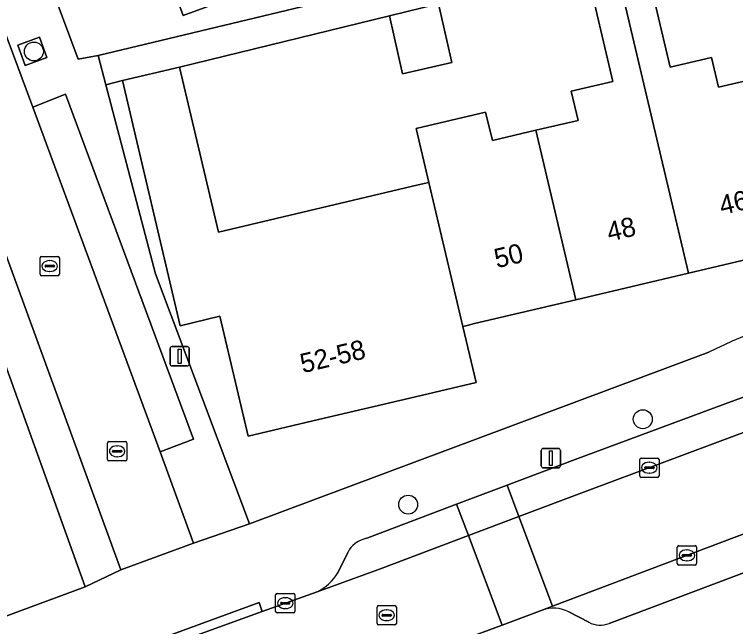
# Model space of a CAD drawing. Extents: x 158472 to 159562, y 388525 to 389606.
# Drawn here: x 159134.37 to 159171.7, y 388714.26 to 388745.92 of the extents above; entities that cross this region are included whole.
import ezdxf

# ---------------------------------------------------------------- set-up
doc = ezdxf.new("R2010")
doc.units = 0
for name, color, linetype in [('IMGEO_Boom', 7, 'Continuous'), ('IMGEO_Erf', 7, 'Continuous'), ('IMGEO_Groenvoorziening', 7, 'Continuous'), ('IMGEO_Kolk', 7, 'Continuous'), ('IMGEO_Lichtmast', 7, 'Continuous'), ('IMGEO_Pand', 7, 'Continuous'), ('IMGEO_Pand_nummerreeks', 7, 'Continuous'), ('IMGEO_Parkeervlak_open', 7, 'Continuous'), ('IMGEO_Rijbaan_lokaal_open', 7, 'Continuous'), ('IMGEO_Rioolput', 7, 'Continuous'), ('IMGEO_Voetpad_open', 7, 'Continuous')]:
    doc.layers.add(name, color=color, linetype=linetype)

msp = doc.modelspace()

# ---------------------------------------------------------------- linework, layer by layer
at = {"layer": 'IMGEO_Boom'}
for centre in [(159135.378, 388744.008), (159166.896, 388724.984), (159154.75, 388720.566)]:
    msp.add_circle(centre, 0.489, dxfattribs=at)
at = {"layer": 'IMGEO_Erf'}
for points in [[(159175.939, 388750), (159175.698, 388751.019), (159166.947, 388748.967), (159168.311, 388743.191), (159170.459, 388743.698), (159170.823, 388742.157), (159173.045, 388742.681), (159175.204, 388743.191), (159174.813, 388744.844), (159177.032, 388745.368)], [(159163.979, 388748.266), (159156.327, 388746.47), (159157.01, 388743.431), (159154.46, 388742.857), (159153.786, 388745.855), (159142.909, 388743.198), (159144.925, 388734.661), (159155.261, 388737.102), (159155.828, 388737.236), (159155.17, 388740.024), (159158.762, 388740.873), (159159.11, 388739.398), (159161.359, 388739.929), (159163.544, 388740.445), (159163.189, 388741.951), (159165.35, 388742.461)]]:
    msp.add_lwpolyline(points, close=True, dxfattribs=at)
for points in [[(159135.295, 388750), (159137.677, 388743.611), (159138.705, 388743.804), (159164.296, 388749.934)], [(159147.79, 388747.598), (159143.098, 388745.87), (159141.577, 388750)], [(159196.529, 388748.231), (159198.597, 388739.472), (159192.637, 388738.064), (159186.796, 388736.685), (159180.954, 388735.305), (159175.112, 388733.925), (159169.27, 388732.546), (159163.428, 388731.166), (159158.186, 388729.928), (159157.805, 388729.838), (159157.587, 388729.786), (159158.27, 388726.892), (159154.834, 388726.08), (159150.112, 388724.965), (159146.469, 388724.104), (159145.004, 388730.308), (159142.954, 388729.823), (159139.96, 388742.501), (159139.106, 388742.277), (159141.671, 388732.512), (159146.544, 388719.568), (159170.31, 388728.457)], [(159090.691, 388698.796), (159138.036, 388716.321), (159133.328, 388729.371), (159130.469, 388728.297), (159129.382, 388731.188)]]:
    msp.add_lwpolyline(points, dxfattribs=at)
msp.add_arc((159185.802, 388696.479), 35.533, 104.3383, 115.8477, dxfattribs=at)
at = {"layer": 'IMGEO_Groenvoorziening'}
msp.add_lwpolyline([(159136.05, 388743.7), (159135.66, 388744.746), (159134.543, 388744.33), (159134.933, 388743.284)], close=True, dxfattribs=at)
at = {"layer": 'IMGEO_Kolk'}
for p, q in [((159135.769, 388733.407), (159136.621, 388733.407)), ((159135.694, 388732.481), (159135.694, 388733.333)), ((159136.182, 388733.187), (159136.207, 388733.187)), ((159136.695, 388733.333), (159136.695, 388732.481)), ((159135.953, 388732.901), (159135.953, 388732.913)), ((159136.391, 388732.864), (159135.993, 388732.864)), ((159135.996, 388732.95), (159136.394, 388732.95)), ((159136.205, 388732.627), (159136.18, 388732.627)), ((159136.437, 388732.913), (159136.437, 388732.901)), ((159136.621, 388732.407), (159135.769, 388732.407)), ((159139.184, 388722.899), (159139.184, 388723.751)), ((159139.259, 388723.825), (159140.111, 388723.825)), ((159140.185, 388723.751), (159140.185, 388722.899)), ((159139.443, 388723.319), (159139.443, 388723.331)), ((159139.486, 388723.368), (159139.884, 388723.368)), ((159139.672, 388723.605), (159139.697, 388723.605)), ((159139.927, 388723.331), (159139.927, 388723.319)), ((159139.881, 388723.282), (159139.483, 388723.282)), ((159139.695, 388723.045), (159139.67, 388723.045)), ((159166.811, 388722.977), (159167.663, 388722.977)), ((159140.111, 388722.825), (159139.259, 388722.825)), ((159166.736, 388722.051), (159166.736, 388722.903)), ((159167.224, 388722.757), (159167.249, 388722.757)), ((159167.737, 388722.903), (159167.737, 388722.051)), ((159166.995, 388722.471), (159166.995, 388722.483)), ((159167.433, 388722.434), (159167.035, 388722.434)), ((159167.038, 388722.52), (159167.436, 388722.52)), ((159167.247, 388722.197), (159167.222, 388722.197)), ((159167.479, 388722.483), (159167.479, 388722.471)), ((159167.663, 388721.977), (159166.811, 388721.977)), ((159168.759, 388718.443), (159169.611, 388718.443)), ((159168.684, 388717.517), (159168.684, 388718.369)), ((159169.172, 388718.223), (159169.197, 388718.223)), ((159169.685, 388718.369), (159169.685, 388717.517)), ((159168.943, 388717.937), (159168.943, 388717.949)), ((159169.381, 388717.9), (159168.983, 388717.9)), ((159168.986, 388717.986), (159169.384, 388717.986)), ((159169.427, 388717.949), (159169.427, 388717.937)), ((159169.611, 388717.443), (159168.759, 388717.443)), ((159169.195, 388717.663), (159169.17, 388717.663)), ((159147.89, 388715.042), (159147.89, 388715.894)), ((159147.965, 388715.968), (159148.817, 388715.968)), ((159148.891, 388715.894), (159148.891, 388715.042)), ((159148.149, 388715.462), (159148.149, 388715.474)), ((159148.192, 388715.511), (159148.59, 388715.511)), ((159148.378, 388715.748), (159148.403, 388715.748)), ((159148.633, 388715.474), (159148.633, 388715.462)), ((159148.587, 388715.425), (159148.189, 388715.425)), ((159148.401, 388715.188), (159148.376, 388715.188)), ((159148.817, 388714.968), (159147.965, 388714.968))]:
    msp.add_line(p, q, dxfattribs=at)
for points in [[(159135.769, 388733.407), (159136.621, 388733.407)], [(159135.694, 388732.481), (159135.694, 388733.333)], [(159136.695, 388733.333), (159136.695, 388732.481)], [(159136.621, 388732.407), (159135.769, 388732.407)], [(159139.184, 388722.899), (159139.184, 388723.751)], [(159139.259, 388723.825), (159140.111, 388723.825)], [(159140.185, 388723.751), (159140.185, 388722.899)], [(159166.811, 388722.977), (159167.663, 388722.977)], [(159140.111, 388722.825), (159139.259, 388722.825)], [(159166.736, 388722.051), (159166.736, 388722.903)], [(159167.737, 388722.903), (159167.737, 388722.051)], [(159167.663, 388721.977), (159166.811, 388721.977)], [(159168.759, 388718.443), (159169.611, 388718.443)], [(159168.684, 388717.517), (159168.684, 388718.369)], [(159169.685, 388718.369), (159169.685, 388717.517)], [(159169.611, 388717.443), (159168.759, 388717.443)], [(159147.89, 388715.042), (159147.89, 388715.894)], [(159147.965, 388715.968), (159148.817, 388715.968)], [(159148.891, 388715.894), (159148.891, 388715.042)], [(159148.817, 388714.968), (159147.965, 388714.968)]]:
    msp.add_lwpolyline(points, dxfattribs=at)
for centre, radius, start, end in [((159135.771, 388733.331), 0.0765, 91.552, 178.448), ((159135.771, 388733.331), 0.0765, 91.552, 178.448), ((159136.619, 388733.331), 0.0765, 1.552, 88.448), ((159136.619, 388733.331), 0.0765, 1.552, 88.448), ((159135.993, 388732.91), 0.0403, 85.8775, 175.7526), ((159135.99, 388732.9), 0.0366, 178.938, 274.7102), ((159136.394, 388732.907), 0.043, 264.8664, 352.4533), ((159136.398, 388732.912), 0.0386, 1.7309, 96.639), ((159135.771, 388732.483), 0.0765, 181.552, 268.448), ((159135.771, 388732.483), 0.0765, 181.552, 268.448), ((159136.619, 388732.483), 0.0765, 271.552, 358.448), ((159136.619, 388732.483), 0.0765, 271.552, 358.448), ((159139.261, 388723.749), 0.0765, 91.552, 178.448), ((159139.261, 388723.749), 0.0765, 91.552, 178.448), ((159140.109, 388723.749), 0.0765, 1.552, 88.448), ((159140.109, 388723.749), 0.0765, 1.552, 88.448), ((159139.483, 388723.328), 0.0403, 85.8775, 175.7526), ((159139.48, 388723.318), 0.0366, 178.938, 274.7102), ((159139.884, 388723.325), 0.043, 264.8664, 352.4533), ((159139.888, 388723.33), 0.0386, 1.7309, 96.639), ((159166.813, 388722.901), 0.0765, 91.552, 178.448), ((159166.813, 388722.901), 0.0765, 91.552, 178.448), ((159167.661, 388722.901), 0.0765, 1.552, 88.448), ((159167.661, 388722.901), 0.0765, 1.552, 88.448), ((159139.261, 388722.901), 0.0765, 181.552, 268.448), ((159139.261, 388722.901), 0.0765, 181.552, 268.448), ((159140.109, 388722.901), 0.0765, 271.552, 358.448), ((159140.109, 388722.901), 0.0765, 271.552, 358.448), ((159167.035, 388722.48), 0.0403, 85.8775, 175.7526), ((159167.032, 388722.47), 0.0366, 178.938, 274.7102), ((159167.436, 388722.477), 0.043, 264.8664, 352.4533), ((159167.44, 388722.482), 0.0386, 1.7309, 96.639), ((159166.813, 388722.053), 0.0765, 181.552, 268.448), ((159166.813, 388722.053), 0.0765, 181.552, 268.448), ((159167.661, 388722.053), 0.0765, 271.552, 358.448), ((159167.661, 388722.053), 0.0765, 271.552, 358.448), ((159168.761, 388718.367), 0.0765, 91.552, 178.448), ((159168.761, 388718.367), 0.0765, 91.552, 178.448), ((159169.609, 388718.367), 0.0765, 1.552, 88.448), ((159169.609, 388718.367), 0.0765, 1.552, 88.448), ((159168.983, 388717.946), 0.0403, 85.8775, 175.7526), ((159168.98, 388717.936), 0.0366, 178.938, 274.7102), ((159169.384, 388717.943), 0.043, 264.8664, 352.4533), ((159169.388, 388717.948), 0.0386, 1.7309, 96.639), ((159168.761, 388717.519), 0.0765, 181.552, 268.448), ((159168.761, 388717.519), 0.0765, 181.552, 268.448), ((159169.609, 388717.519), 0.0765, 271.552, 358.448), ((159169.609, 388717.519), 0.0765, 271.552, 358.448), ((159147.967, 388715.892), 0.0765, 91.552, 178.448), ((159147.967, 388715.892), 0.0765, 91.552, 178.448), ((159148.815, 388715.892), 0.0765, 1.552, 88.448), ((159148.815, 388715.892), 0.0765, 1.552, 88.448), ((159148.189, 388715.471), 0.0403, 85.8775, 175.7526), ((159148.186, 388715.461), 0.0366, 178.938, 274.7102), ((159148.59, 388715.468), 0.043, 264.8664, 352.4533), ((159148.594, 388715.473), 0.0386, 1.7309, 96.639), ((159147.967, 388715.044), 0.0765, 181.552, 268.448), ((159147.967, 388715.044), 0.0765, 181.552, 268.448), ((159148.815, 388715.044), 0.0765, 271.552, 358.448), ((159148.815, 388715.044), 0.0765, 271.552, 358.448)]:
    msp.add_arc(centre, radius, start, end, dxfattribs=at)
for centre, major_axis, ratio, start_param, end_param in [((159136.181, 388732.907), (-0.387, 0.002), 0.722429, 4.712389, 7.853982), ((159136.206, 388732.907), (-0.39, 0.002), 0.717154, 1.570796, 4.712389), ((159139.671, 388723.325), (-0.387, 0.002), 0.722429, 4.712389, 7.853982), ((159139.696, 388723.325), (-0.39, 0.002), 0.717154, 1.570796, 4.712389), ((159167.223, 388722.477), (-0.387, 0.002), 0.722429, 4.712389, 7.853982), ((159167.248, 388722.477), (-0.39, 0.002), 0.717154, 1.570796, 4.712389), ((159169.171, 388717.943), (-0.387, 0.002), 0.722429, 4.712389, 7.853982), ((159169.196, 388717.943), (-0.39, 0.002), 0.717154, 1.570796, 4.712389), ((159148.377, 388715.468), (-0.387, 0.002), 0.722429, 4.712389, 7.853982), ((159148.402, 388715.468), (-0.39, 0.002), 0.717154, 1.570796, 4.712389)]:
    msp.add_ellipse(centre, major_axis=major_axis, ratio=ratio, start_param=start_param, end_param=end_param, dxfattribs=at)
at = {"layer": 'IMGEO_Lichtmast'}
for p, q in [((159142.425, 388727.84), (159142.425, 388728.64)), ((159142.425, 388728.64), (159142.425, 388727.84)), ((159142.525, 388728.74), (159143.315, 388728.74)), ((159143.315, 388728.74), (159142.525, 388728.74)), ((159143.415, 388728.64), (159143.415, 388727.84)), ((159143.415, 388727.84), (159143.415, 388728.64)), ((159143.315, 388727.74), (159142.525, 388727.74)), ((159142.525, 388727.74), (159143.315, 388727.74)), ((159161.642, 388722.57), (159161.642, 388723.37)), ((159161.642, 388723.37), (159161.642, 388722.57)), ((159161.742, 388723.47), (159162.532, 388723.47)), ((159162.532, 388723.47), (159161.742, 388723.47)), ((159162.632, 388723.37), (159162.632, 388722.57)), ((159162.632, 388722.57), (159162.632, 388723.37)), ((159162.532, 388722.47), (159161.742, 388722.47)), ((159161.742, 388722.47), (159162.532, 388722.47))]:
    msp.add_line(p, q, dxfattribs=at)
for points in [[(159142.845, 388728.615), (159142.995, 388728.615), (159142.995, 388727.865), (159142.845, 388727.865), (159142.845, 388728.615)], [(159162.062, 388723.345), (159162.212, 388723.345), (159162.212, 388722.595), (159162.062, 388722.595), (159162.062, 388723.345)]]:
    msp.add_lwpolyline(points, dxfattribs=at)
for centre, start, end in [((159142.525, 388728.64), 90, 180), ((159142.525, 388728.64), 90, 180), ((159143.315, 388728.64), 0, 90), ((159143.315, 388728.64), 360, 90), ((159142.525, 388727.84), 180, 270), ((159142.525, 388727.84), 180, 270), ((159143.315, 388727.84), 270, 0), ((159143.315, 388727.84), 270, 0), ((159161.742, 388723.37), 90, 180), ((159161.742, 388723.37), 90, 180), ((159162.532, 388723.37), 0, 90), ((159162.532, 388723.37), 360, 90), ((159161.742, 388722.57), 180, 270), ((159161.742, 388722.57), 180, 270), ((159162.532, 388722.57), 270, 0), ((159162.532, 388722.57), 270, 0)]:
    msp.add_arc(centre, 0.1, start, end, dxfattribs=at)
at = {"layer": 'IMGEO_Pand'}
for points in [[(159150.965, 388750), (159149.453, 388754.103), (159149.236, 388754.023), (159141.187, 388751.058), (159141.577, 388750), (159143.098, 388745.87), (159147.79, 388747.598), (159151.364, 388748.915)], [(159175.112, 388733.925), (159173.045, 388742.681), (159170.823, 388742.157), (159170.459, 388743.698), (159168.311, 388743.191), (159166.947, 388748.967), (159165.475, 388748.619), (159169.27, 388732.546)], [(159161.359, 388739.929), (159163.428, 388731.166), (159169.27, 388732.546), (159165.475, 388748.619), (159163.979, 388748.266), (159165.35, 388742.461), (159163.189, 388741.951), (159163.544, 388740.445)], [(159154.46, 388742.857), (159157.01, 388743.431), (159156.327, 388746.47), (159153.786, 388745.855)], [(159155.828, 388737.236), (159155.261, 388737.102), (159144.925, 388734.661), (159142.909, 388743.198), (159139.96, 388742.501), (159142.954, 388729.823), (159145.004, 388730.308), (159146.469, 388724.104), (159150.112, 388724.965), (159154.834, 388726.08), (159158.27, 388726.892), (159157.587, 388729.786)], [(159161.359, 388739.929), (159159.11, 388739.398), (159158.762, 388740.873), (159155.17, 388740.024), (159155.828, 388737.236), (159157.587, 388729.786), (159157.805, 388729.838), (159158.186, 388729.928), (159163.428, 388731.166)]]:
    msp.add_lwpolyline(points, close=True, dxfattribs=at)
at = {"layer": 'IMGEO_Parkeervlak_open'}
for points in [[(159137.016, 388741.799), (159135.321, 388741.121), (159141.907, 388723.296), (159143.633, 388723.953)], [(159159.88, 388721.567), (159157.262, 388720.582), (159157.871, 388718.963), (159160.489, 388719.947)]]:
    msp.add_lwpolyline(points, close=True, dxfattribs=at)
for points in [[(159178.125, 388728.335), (159171.168, 388725.789), (159163.405, 388722.893), (159159.88, 388721.567), (159160.489, 388719.947), (159164.012, 388721.272), (159171.791, 388724.175), (159178.672, 388726.694)], [(159157.871, 388718.963), (159157.262, 388720.582), (159152.661, 388718.852), (159152.546, 388718.81)], [(159173.174, 388719.453), (159162.231, 388715.317), (159161.695, 388715.114)], [(159150.038, 388716.062), (159153.26, 388717.228), (159157.871, 388718.963)], [(159151.625, 388718.089), (159151.108, 388717.042)], [(159165.157, 388714.414), (159173.849, 388717.701)], [(159163.061, 388715.018), (159164.101, 388714.479)]]:
    msp.add_lwpolyline(points, dxfattribs=at)
for centre, radius, start, end in [((159152.873, 388717.444), 1.405, 103.4532, 152.6577), ((159148.968, 388718.304), 2.484, 295.5053, 329.4671), ((159162.268, 388713.494), 1.718, 62.4901, 109.4699), ((159164.704, 388715.665), 1.33, 243.0418, 289.9136)]:
    msp.add_arc(centre, radius, start, end, dxfattribs=at)
at = {"layer": 'IMGEO_Rijbaan_lokaal_open'}
for points in [[(159135.321, 388741.121), (159134, 388744.695), (159130.295, 388743.326), (159131.692, 388739.556), (159139.87, 388717.199), (159143.641, 388718.565), (159141.907, 388723.296)], [(159160.489, 388719.947), (159157.871, 388718.963), (159159.611, 388714.339), (159161.695, 388715.114), (159162.231, 388715.317)], [(159150.006, 388710.766), (159150.389, 388710.909), (159157.459, 388713.538), (159159.611, 388714.339), (159157.871, 388718.963), (159153.26, 388717.228), (159150.038, 388716.062), (159147.197, 388715.034), (159144.005, 388713.879), (159139.387, 388712.169), (159134.579, 388710.389), (159133.876, 388710.139), (159126.21, 388707.414), (159121.757, 388705.716), (159123.494, 388701.022), (159138.476, 388706.537), (159145.31, 388709.044)]]:
    msp.add_lwpolyline(points, close=True, dxfattribs=at)
msp.add_lwpolyline([(159178.672, 388726.694), (159171.791, 388724.175), (159164.012, 388721.272), (159160.489, 388719.947), (159162.231, 388715.317), (159173.174, 388719.453)], dxfattribs=at)
at = {"layer": 'IMGEO_Rioolput'}
for p, q in [((159153.139, 388714.418), (159153.139, 388715.27)), ((159153.214, 388715.344), (159154.066, 388715.344)), ((159153.627, 388715.124), (159153.652, 388715.124)), ((159154.14, 388715.27), (159154.14, 388714.418)), ((159153.398, 388714.838), (159153.398, 388714.85)), ((159153.836, 388714.801), (159153.438, 388714.801)), ((159153.441, 388714.887), (159153.839, 388714.887)), ((159153.882, 388714.85), (159153.882, 388714.838)), ((159154.066, 388714.344), (159153.214, 388714.344)), ((159153.65, 388714.564), (159153.625, 388714.564))]:
    msp.add_line(p, q, dxfattribs=at)
for points in [[(159153.139, 388714.418), (159153.139, 388715.27)], [(159153.214, 388715.344), (159154.066, 388715.344)], [(159154.14, 388715.27), (159154.14, 388714.418)], [(159154.066, 388714.344), (159153.214, 388714.344)]]:
    msp.add_lwpolyline(points, dxfattribs=at)
for centre, radius, start, end in [((159153.216, 388715.268), 0.0765, 91.552, 178.448), ((159153.216, 388715.268), 0.0765, 91.552, 178.448), ((159154.064, 388715.268), 0.0765, 1.552, 88.448), ((159154.064, 388715.268), 0.0765, 1.552, 88.448), ((159153.438, 388714.847), 0.0403, 85.8775, 175.7526), ((159153.435, 388714.837), 0.0366, 178.938, 274.7102), ((159153.839, 388714.844), 0.043, 264.8664, 352.4533), ((159153.843, 388714.849), 0.0386, 1.7309, 96.639), ((159153.216, 388714.42), 0.0765, 181.552, 268.448), ((159153.216, 388714.42), 0.0765, 181.552, 268.448), ((159154.064, 388714.42), 0.0765, 271.552, 358.448), ((159154.064, 388714.42), 0.0765, 271.552, 358.448)]:
    msp.add_arc(centre, radius, start, end, dxfattribs=at)
for centre, major_axis, ratio, start_param, end_param in [((159153.626, 388714.844), (-0.387, 0.002), 0.722429, 4.712389, 7.853982), ((159153.651, 388714.844), (-0.39, 0.002), 0.717154, 1.570796, 4.712389)]:
    msp.add_ellipse(centre, major_axis=major_axis, ratio=ratio, start_param=start_param, end_param=end_param, dxfattribs=at)
at = {"layer": 'IMGEO_Voetpad_open'}
for points in [[(159141.671, 388732.512), (159139.106, 388742.277), (159138.705, 388743.804), (159137.677, 388743.611), (159135.295, 388750), (159122.414, 388784.582), (159122.066, 388785.517), (159120.978, 388785.165), (159127.745, 388766.92), (159126.03, 388766.263), (159132.04, 388750), (159133.019, 388747.35), (159134, 388744.695), (159135.321, 388741.121), (159137.016, 388741.799), (159143.633, 388723.953), (159141.907, 388723.296), (159143.641, 388718.565), (159146.544, 388719.568)], [(159122.228, 388765.087), (159117.62, 388763.408), (159110.821, 388781.983), (159110.164, 388781.46), (159116.974, 388763.207), (159117.478, 388761.857), (159119.842, 388762.718), (159124.542, 388750), (159129.343, 388737.007), (159129.851, 388735.632), (159130.836, 388736.002), (159132.25, 388732.24), (159133.328, 388729.371), (159138.036, 388716.321), (159139.87, 388717.199), (159131.692, 388739.556), (159130.295, 388743.326), (159129.311, 388745.98), (159127.821, 388750)], [(159134.933, 388743.284), (159134.543, 388744.33), (159135.66, 388744.746), (159136.05, 388743.7)], [(159147.197, 388715.034), (159147.03, 388715.504), (159139.22, 388712.639), (159139.387, 388712.169), (159144.005, 388713.879)]]:
    msp.add_lwpolyline(points, close=True, dxfattribs=at)
for points in [[(159164.296, 388749.934), (159138.705, 388743.804), (159139.106, 388742.277), (159139.96, 388742.501), (159142.909, 388743.198), (159153.786, 388745.855), (159156.327, 388746.47)], [(159170.31, 388728.457), (159146.544, 388719.568), (159143.641, 388718.565), (159139.87, 388717.199), (159138.036, 388716.321), (159090.691, 388698.796)], [(159159.88, 388721.567), (159163.405, 388722.893), (159171.168, 388725.789), (159178.125, 388728.335)], [(159152.546, 388718.81), (159152.661, 388718.852), (159157.262, 388720.582), (159159.88, 388721.567)], [(159151.108, 388717.042), (159151.625, 388718.089)], [(159173.849, 388717.701), (159165.157, 388714.414)], [(159133.876, 388710.139), (159134.579, 388710.389), (159139.387, 388712.169), (159139.22, 388712.639), (159147.03, 388715.504), (159147.197, 388715.034), (159150.038, 388716.062)], [(159161.695, 388715.114), (159159.611, 388714.339), (159157.459, 388713.538), (159157.628, 388713.068), (159150.558, 388710.439), (159150.389, 388710.909), (159150.006, 388710.766), (159145.31, 388709.044)], [(159164.101, 388714.479), (159163.061, 388715.018)]]:
    msp.add_lwpolyline(points, dxfattribs=at)
for centre, radius, start, end in [((159185.802, 388696.479), 35.533, 104.3383, 115.8477), ((159152.873, 388717.444), 1.405, 103.4532, 152.6577), ((159148.968, 388718.304), 2.484, 295.5053, 329.4671), ((159162.268, 388713.494), 1.718, 62.4901, 109.4699), ((159164.704, 388715.665), 1.33, 243.0418, 289.9136)]:
    msp.add_arc(centre, radius, start, end, dxfattribs=at)

# ---------------------------------------------------------------- texts
at = {"layer": 'IMGEO_Pand_nummerreeks'}
for s, rotation, p in [('46', 13.2883, (159170.99, 388735.541)), ('48', 13.2883, (159165.166, 388734.165)), ('50', 13.2869, (159159.339, 388732.789)), ('52-58', 13.2926, (159149.292, 388727.361))]:
    msp.add_text(s, height=1, rotation=rotation, dxfattribs=at).set_placement(p)

doc.saveas('drawing.dxf')
